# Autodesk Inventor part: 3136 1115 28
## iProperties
Shininess: 20.0
Length Units: 11269
Angle Units: 11279
Time Units: 11290
Mass Units: 11283
Length Display Precision: 3
Angle Display Precision: 2
Compacted: True
Created: 2000-11
Part Number: 3136 1115 28
Material: Steel, Mild
Document SubType Name: Modeling
Designer: Joe M
Engineer: Joe M
Density: 0.0
Volumn: 0.0
Area: 0.0
PropertySet Name: Model Information
Control State: 0
Master: False
Checked Out: False
Last Check In By: brpog
Last Check In Date: 2001-02-28
Author: Joe M
